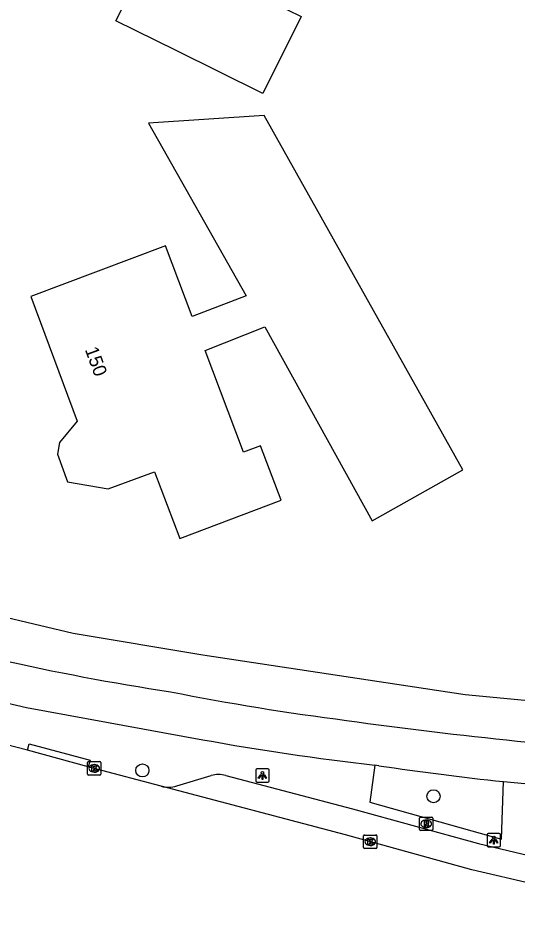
# Model space of a CAD drawing. Extents: x 160037 to 160839, y 385326 to 386441.
# Drawn here: x 160702.7 to 160739.9, y 385329.1 to 385395.6 of the extents above; entities that cross this region are included whole.
import ezdxf

# ---------------------------------------------------------------- set-up
doc = ezdxf.new("R2010")
doc.units = 0
for name, color, linetype in [('IMGEO_Boom', 7, 'Continuous'), ('IMGEO_Fietspad_gesloten', 7, 'Continuous'), ('IMGEO_Kolk', 7, 'Continuous'), ('IMGEO_Lichtpunt', 7, 'Continuous'), ('IMGEO_Pand', 7, 'Continuous'), ('IMGEO_Pand_nummerreeks', 7, 'Continuous'), ('IMGEO_Rijbaan_lokaal_gesloten', 7, 'Continuous'), ('IMGEO_Rioolput', 7, 'Continuous'), ('IMGEO_Voetpad_open', 7, 'Continuous')]:
    doc.layers.add(name, color=color, linetype=linetype)

msp = doc.modelspace()

# ---------------------------------------------------------------- linework, layer by layer
at = {"layer": 'IMGEO_Boom'}
for centre in [(160712.015, 385339.472), (160733.703, 385337.546)]:
    msp.add_circle(centre, 0.489, dxfattribs=at)
at = {"layer": 'IMGEO_Fietspad_gesloten'}
for points in [[(160692.699, 385346.641), (160703.387, 385344.166), (160716.51, 385341.759)], [(160729.624, 385339.823), (160729.48, 385339.84), (160729.336, 385339.856)], [(160738.919, 385338.641), (160742.627, 385338.286)]]:
    msp.add_lwpolyline(points, dxfattribs=at)
for centre, radius, start, end in [((160742.565, 385530.57), 187.415, 257.26507, 261.26988), ((160753.888, 385548.59), 207.118, 258.92984, 262.60251), ((160779.744, 385724.113), 384.521, 262.14925, 264.0579), ((160752.977, 385543.368), 204.88, 259.7472, 263.37393), ((160772.805, 385655.122), 315.183, 264.01411, 266.39838), ((160761.195, 385550.956), 213.481, 261.49539, 264.01035)]:
    msp.add_arc(centre, radius, start, end, dxfattribs=at)
at = {"layer": 'IMGEO_Kolk'}
for p, q in [((160707.929, 385339.198), (160707.929, 385340.05)), ((160708.004, 385340.124), (160708.856, 385340.124)), ((160708.417, 385339.904), (160708.442, 385339.904)), ((160708.93, 385340.05), (160708.93, 385339.198)), ((160708.44, 385339.344), (160708.415, 385339.344)), ((160708.856, 385339.124), (160708.004, 385339.124)), ((160728.494, 385333.731), (160728.494, 385334.583)), ((160728.569, 385334.657), (160729.421, 385334.657)), ((160729.495, 385334.583), (160729.495, 385333.731)), ((160729.005, 385333.877), (160728.98, 385333.877)), ((160728.982, 385334.437), (160729.007, 385334.437)), ((160729.421, 385333.657), (160728.569, 385333.657))]:
    msp.add_line(p, q, dxfattribs=at)
for points in [[(160707.929, 385339.198), (160707.929, 385340.05)], [(160708.004, 385340.124), (160708.856, 385340.124)], [(160708.93, 385340.05), (160708.93, 385339.198)], [(160708.25, 385339.824), (160708.373, 385339.824), (160708.373, 385339.673), (160708.503, 385339.824), (160708.667, 385339.824), (160708.521, 385339.673), (160708.674, 385339.424), (160708.522, 385339.424), (160708.437, 385339.588), (160708.373, 385339.521), (160708.373, 385339.424), (160708.25, 385339.424), (160708.25, 385339.824)], [(160708.856, 385339.124), (160708.004, 385339.124)], [(160728.494, 385333.731), (160728.494, 385334.583)], [(160728.569, 385334.657), (160729.421, 385334.657)], [(160729.495, 385334.583), (160729.495, 385333.731)], [(160728.815, 385334.357), (160728.938, 385334.357), (160728.938, 385334.206), (160729.068, 385334.357), (160729.232, 385334.357), (160729.086, 385334.206), (160729.239, 385333.957), (160729.087, 385333.957), (160729.002, 385334.121), (160728.938, 385334.054), (160728.938, 385333.957), (160728.815, 385333.957), (160728.815, 385334.357)], [(160729.421, 385333.657), (160728.569, 385333.657)]]:
    msp.add_lwpolyline(points, dxfattribs=at)
for centre, start, end in [((160708.006, 385340.048), 91.55205, 178.44795), ((160708.006, 385340.048), 91.55205, 178.44795), ((160708.854, 385340.048), 1.55205, 88.44795), ((160708.854, 385340.048), 1.55205, 88.44795), ((160708.006, 385339.2), 181.55205, 268.44795), ((160708.006, 385339.2), 181.55205, 268.44795), ((160708.854, 385339.2), 271.55205, 358.44795), ((160708.854, 385339.2), 271.55205, 358.44795), ((160728.571, 385334.581), 91.55205, 178.44795), ((160728.571, 385334.581), 91.55205, 178.44795), ((160729.419, 385334.581), 1.55205, 88.44795), ((160729.419, 385334.581), 1.55205, 88.44795), ((160728.571, 385333.733), 181.55205, 268.44795), ((160728.571, 385333.733), 181.55205, 268.44795), ((160729.419, 385333.733), 271.55205, 358.44795), ((160729.419, 385333.733), 271.55205, 358.44795)]:
    msp.add_arc(centre, 0.0765, start, end, dxfattribs=at)
for centre, major_axis, ratio, start_param, end_param in [((160708.416, 385339.624), (-0.387, 0.002), 0.722429, 4.712389, 7.853982), ((160708.441, 385339.624), (-0.39, 0.002), 0.717154, 1.570796, 4.712389), ((160728.981, 385334.157), (-0.387, 0.002), 0.722429, 4.712389, 7.853982), ((160729.006, 385334.157), (-0.39, 0.002), 0.717154, 1.570796, 4.712389)]:
    msp.add_ellipse(centre, major_axis=major_axis, ratio=ratio, start_param=start_param, end_param=end_param, dxfattribs=at)
at = {"layer": 'IMGEO_Lichtpunt'}
for p, q in [((160720.457, 385339.499), (160720.457, 385338.692)), ((160720.457, 385339.499), (160720.457, 385338.692)), ((160721.359, 385339.594), (160720.551, 385339.594)), ((160721.359, 385339.594), (160720.551, 385339.594)), ((160721.453, 385338.692), (160721.453, 385339.499)), ((160721.453, 385338.692), (160721.453, 385339.499)), ((160720.551, 385338.598), (160721.359, 385338.598)), ((160720.551, 385338.598), (160721.359, 385338.598)), ((160737.694, 385334.68), (160737.694, 385333.873)), ((160737.694, 385334.68), (160737.694, 385333.873)), ((160738.596, 385334.775), (160737.788, 385334.775)), ((160738.596, 385334.775), (160737.788, 385334.775)), ((160738.69, 385333.873), (160738.69, 385334.68)), ((160738.69, 385333.873), (160738.69, 385334.68)), ((160737.788, 385333.779), (160738.596, 385333.779)), ((160737.788, 385333.779), (160738.596, 385333.779))]:
    msp.add_line(p, q, dxfattribs=at)
for points in [[(160720.831, 385339.163), (160720.87, 385339.135), (160720.682, 385338.873), (160720.644, 385338.9), (160720.831, 385339.163)], [(160721.043, 385339.135), (160721.081, 385339.162), (160721.268, 385338.9), (160721.229, 385338.872), (160721.043, 385339.135)], [(160720.933, 385339.115), (160720.98, 385339.115), (160720.98, 385338.793), (160720.933, 385338.793), (160720.933, 385339.115)], [(160738.068, 385334.344), (160738.107, 385334.316), (160737.919, 385334.054), (160737.881, 385334.081), (160738.068, 385334.344)], [(160738.17, 385334.296), (160738.217, 385334.296), (160738.217, 385333.974), (160738.17, 385333.974), (160738.17, 385334.296)], [(160738.28, 385334.316), (160738.318, 385334.343), (160738.505, 385334.081), (160738.466, 385334.053), (160738.28, 385334.316)]]:
    msp.add_lwpolyline(points, dxfattribs=at)
for centre in [(160720.956, 385339.297), (160738.193, 385334.478)]:
    msp.add_circle(centre, 0.0994, dxfattribs=at)
for centre, start, end in [((160720.551, 385339.499), 90, 180), ((160720.551, 385339.499), 90, 180), ((160721.359, 385339.499), 0, 90), ((160721.359, 385339.499), 0, 90), ((160720.551, 385338.692), 180, 270), ((160720.551, 385338.692), 180, 270), ((160721.359, 385338.692), 270, 0), ((160721.359, 385338.692), 270, 360), ((160737.788, 385334.68), 90, 180), ((160737.788, 385334.68), 90, 180), ((160738.596, 385334.68), 0, 90), ((160738.596, 385334.68), 0, 90), ((160737.788, 385333.873), 180, 270), ((160737.788, 385333.873), 180, 270), ((160738.596, 385333.873), 270, 0), ((160738.596, 385333.873), 270, 360)]:
    msp.add_arc(centre, 0.0946, start, end, dxfattribs=at)
at = {"layer": 'IMGEO_Pand'}
for points in [[(160723.254, 385407.578), (160723.163, 385407.328), (160726.265, 385406.201), (160724.556, 385401.504), (160722.623, 385402.207), (160720.797, 385397.188), (160723.834, 385395.683), (160720.982, 385389.93), (160714.527, 385393.131), (160710.047, 385395.352), (160711.179, 385397.635), (160706.794, 385399.234), (160708.065, 385402.688), (160707.585, 385402.862), (160709.802, 385408.94), (160710.93, 385408.529), (160716.529, 385406.487), (160717.67, 385409.615)], [(160707.161, 385365.502), (160705.844, 385363.925), (160705.69, 385363.036), (160706.44, 385360.99), (160709.455, 385360.467), (160712.911, 385361.736), (160714.812, 385356.754), (160722.357, 385359.606), (160720.819, 385363.675), (160719.556, 385363.198), (160716.692, 385370.774), (160721.143, 385372.533), (160729.126, 385358.069), (160735.882, 385361.888), (160721.097, 385388.283), (160712.478, 385387.715), (160719.736, 385374.845), (160715.734, 385373.298), (160713.74, 385378.585), (160703.707, 385374.801), (160707.161, 385365.502)]]:
    msp.add_lwpolyline(points, dxfattribs=at)
at = {"layer": 'IMGEO_Rijbaan_lokaal_gesloten'}
for points in [[(160703.461, 385340.974), (160691.683, 385344.017)], [(160707.987, 385339.743), (160703.461, 385340.974)], [(160713.421, 385338.288), (160708.514, 385339.6), (160707.987, 385339.743)], [(160814.938, 385332.019), (160803.859, 385331.45), (160790.905, 385330.813), (160777.182, 385330.203), (160764.726, 385329.528), (160755.648, 385329.055), (160750.651, 385329.226), (160745.523, 385329.896), (160742.313, 385330.683), (160741.253, 385330.969), (160736.562, 385332.071), (160727.15, 385334.664), (160713.421, 385338.288)]]:
    msp.add_lwpolyline(points, dxfattribs=at)
at = {"layer": 'IMGEO_Rioolput'}
for p, q in [((160732.661, 385335.069), (160732.661, 385335.921)), ((160732.736, 385335.995), (160733.588, 385335.995)), ((160733.662, 385335.921), (160733.662, 385335.069)), ((160733.172, 385335.215), (160733.147, 385335.215)), ((160733.149, 385335.775), (160733.174, 385335.775)), ((160733.588, 385334.995), (160732.736, 385334.995))]:
    msp.add_line(p, q, dxfattribs=at)
for points in [[(160732.661, 385335.069), (160732.661, 385335.921)], [(160732.736, 385335.995), (160733.588, 385335.995)], [(160733.662, 385335.921), (160733.662, 385335.069)], [(160733.25, 385335.693), (160732.998, 385335.695), (160732.998, 385335.295)], [(160732.998, 385335.295), (160733.122, 385335.295), (160733.122, 385335.457), (160733.133, 385335.457)], [(160733.176, 385335.614), (160733.122, 385335.614), (160733.122, 385335.533)], [(160733.122, 385335.533), (160733.174, 385335.533)], [(160733.18, 385335.428), (160733.251, 385335.295), (160733.391, 385335.295), (160733.326, 385335.421)], [(160733.588, 385334.995), (160732.736, 385334.995)]]:
    msp.add_lwpolyline(points, dxfattribs=at)
for centre, radius, start, end in [((160732.738, 385335.919), 0.0765, 91.55205, 178.44795), ((160732.738, 385335.919), 0.0765, 91.55205, 178.44795), ((160733.586, 385335.919), 0.0765, 1.55205, 88.44795), ((160733.586, 385335.919), 0.0765, 1.55205, 88.44795), ((160733.132, 385335.404), 0.0533, 26.02933, 88.69889), ((160733.158, 385335.722), 0.19, 274.7715, 282.96867), ((160733.182, 385335.518), 0.0964, 77.00612, 93.18647), ((160733.196, 385335.575), 0.0378, 276.66336, 79.67722), ((160733.249, 385335.583), 0.109, 350.36119, 89.41601), ((160733.247, 385335.583), 0.112, 277.58423, 350.98172), ((160733.231, 385335.368), 0.108, 29.51342, 73.79051), ((160732.738, 385335.071), 0.0765, 181.55205, 268.44795), ((160732.738, 385335.071), 0.0765, 181.55205, 268.44795), ((160733.586, 385335.071), 0.0765, 271.55205, 358.44795), ((160733.586, 385335.071), 0.0765, 271.55205, 358.44795)]:
    msp.add_arc(centre, radius, start, end, dxfattribs=at)
for centre, major_axis, ratio, start_param, end_param in [((160733.148, 385335.495), (-0.387, 0.002), 0.722429, 4.712389, 7.853982), ((160733.173, 385335.495), (-0.39, 0.002), 0.717154, 1.570796, 4.712389)]:
    msp.add_ellipse(centre, major_axis=major_axis, ratio=ratio, start_param=start_param, end_param=end_param, dxfattribs=at)
at = {"layer": 'IMGEO_Voetpad_open'}
for points in [[(160817.935, 385344.075), (160798.343, 385343.507), (160795.007, 385343.265), (160775.15, 385342.953), (160765.401, 385343.108), (160745.489, 385344.203), (160736.06, 385345.098), (160716.52, 385348.053), (160706.87, 385349.675), (160690.096, 385353.665), (160690.02, 385353.684), (160689.944, 385353.705)], [(160703.461, 385340.974), (160703.593, 385341.456), (160708.119, 385340.225), (160707.987, 385339.743)], [(160729.336, 385339.856), (160728.951, 385337.108), (160738.78, 385334.355), (160738.919, 385338.641)], [(160714.576, 385338.317), (160717.146, 385339.081)], [(160718.226, 385339.097), (160727.673, 385336.603), (160737.058, 385334.018), (160738.725, 385333.626), (160741.745, 385332.917), (160742.42, 385332.735), (160742.814, 385332.629), (160745.893, 385331.873), (160750.816, 385331.23), (160755.63, 385331.066), (160760.089, 385331.298), (160760.87, 385331.339), (160764.619, 385331.534), (160769.663, 385331.807), (160771.025, 385331.881), (160777.083, 385332.209), (160787.154, 385332.657), (160790.811, 385332.82), (160795.604, 385333.055), (160803.758, 385333.456), (160811.806, 385333.871)]]:
    msp.add_lwpolyline(points, dxfattribs=at)
for centre, radius, start, end in [((160717.715, 385337.156), 2.008, 75.24298, 106.45455), ((160713.947, 385340.361), 2.138, 255.7643, 287.11229)]:
    msp.add_arc(centre, radius, start, end, dxfattribs=at)

# ---------------------------------------------------------------- texts
at = {"layer": 'IMGEO_Pand_nummerreeks'}
msp.add_text('150', height=1, rotation=290.15843, dxfattribs=at).set_placement((160707.72, 385370.844))

doc.saveas('drawing.dxf')
